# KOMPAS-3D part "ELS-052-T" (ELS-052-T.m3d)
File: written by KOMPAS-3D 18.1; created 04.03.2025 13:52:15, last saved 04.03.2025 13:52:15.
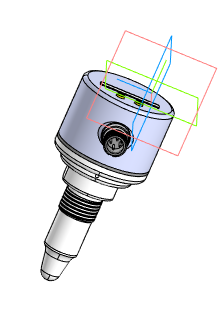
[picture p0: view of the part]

Document properties: Полное имя файла: .

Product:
- Part/product: ELS-052-T
    Масса: 0.976604
  - Body: LC0001
      Масса: 0.0808188
  - Body: LC0001
      Масса: 0.000247181
  - Body: LC0001
      Масса: 0.00580785
  - Body: LC0001
      Масса: 0.00518708
  - Body: LC0001
      Масса: 0.00833853
  - Body: LC0001
      Масса: 0.0516211
  - Body: LC0001
      Масса: 0.454908
  - Body: LC0001
      Масса: 0.055478
  - Body: LC0001
      Масса: 0.171056
  - Body: LC0001
      Масса: 0.112934
  - Body: LC0001
      Масса: 0.0299597

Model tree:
1. Операция без истории:1
2. Операция без истории:2  (labels: ФІЅЗ2)
3. Операция без истории:3  (labels: ФІЅЗ2)
4. Операция без истории:4
5. Операция без истории:5  (labels: µ№ЅЗ7)
6. Операция без истории:6
7. Операция без истории:7
8. Операция без истории:8
9. Операция без истории:9  (labels: РэЧЄ1)
10. Операция без истории:10  (labels: ТЖ¶ЇГж1)
11. Операция без истории:11
12. Операция без истории:12  (labels: ФІЅЗ2; µ№ЅЗ7; РэЧЄ1; ТЖ¶ЇГж1)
